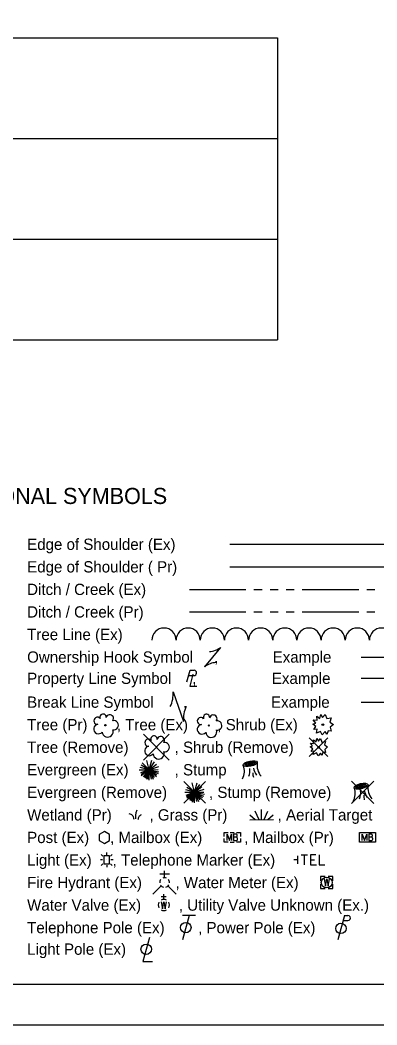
# Model space of a CAD drawing. Extents: x 0 to 34, y 0 to 22.
# Drawn here: x 8.09 to 12.52, y 0 to 12.48 of the extents above; entities that cross this region are included whole.
import ezdxf

# ---------------------------------------------------------------- set-up
doc = ezdxf.new("R2010")
doc.units = 0
for name, color, linetype in [('Default', 7, 'Continuous'), ('SH_Border', 7, 'Continuous'), ('SH_Cut_Line', 7, 'Continuous'), ('SH_Text', 7, 'Continuous')]:
    doc.layers.add(name, color=color, linetype=linetype)

msp = doc.modelspace()

# ---------------------------------------------------------------- linework, layer by layer
at = {"layer": 'Default'}
for p, q in [((6.983, 12.257), (11.289, 12.257)), ((11.289, 12.257), (11.289, 11.007)), ((6.983, 11.007), (11.289, 11.007)), ((6.983, 11.007), (11.289, 11.007)), ((11.289, 11.007), (11.289, 9.757)), ((6.983, 9.757), (11.289, 9.757)), ((6.983, 9.757), (11.289, 9.757)), ((11.289, 9.757), (11.289, 8.507)), ((6.983, 8.507), (11.289, 8.507))]:
    msp.add_line(p, q, dxfattribs=at)
at = {"layer": 'SH_Border'}
msp.add_lwpolyline([(1.5, 21.5), (33.5, 21.5), (33.5, 0.5), (1.5, 0.5)], close=True, dxfattribs=at)
at = {"layer": 'SH_Cut_Line'}
msp.add_lwpolyline([(0, 0), (34, 0), (34, 22), (0, 22)], close=True, dxfattribs=at)
at = {"layer": 'SH_Text'}
for p, q in [((10.698, 5.968), (14.181, 5.968)), ((10.698, 5.688), (14.181, 5.688)), ((10.197, 5.408), (10.897, 5.408)), ((10.997, 5.408), (11.097, 5.408)), ((11.197, 5.408), (11.297, 5.408)), ((11.397, 5.408), (11.497, 5.408)), ((11.597, 5.408), (12.297, 5.408)), ((12.397, 5.408), (12.497, 5.408)), ((10.197, 5.128), (10.897, 5.128)), ((10.997, 5.128), (11.097, 5.128)), ((11.197, 5.128), (11.297, 5.128)), ((11.397, 5.128), (11.497, 5.128)), ((11.597, 5.128), (12.297, 5.128)), ((12.397, 5.128), (12.497, 5.128)), ((10.385, 4.448), (10.585, 4.688)), ((10.485, 4.568), (10.485, 4.568)), ((12.328, 4.568), (14.11, 4.568)), ((10.185, 4.337), (10.25, 4.337)), ((10.225, 4.306), (10.225, 4.306)), ((12.328, 4.304), (14.11, 4.304)), ((9.992, 4.137), (10.122, 3.769)), ((12.328, 4.008), (13.093, 4.008)), ((10.057, 3.953), (10.057, 3.953)), ((9.625, 3.609), (9.946, 3.288)), ((9.946, 3.609), (9.625, 3.288)), ((11.684, 3.564), (11.916, 3.333)), ((11.916, 3.564), (11.684, 3.333)), ((9.786, 3.448), (9.786, 3.448)), ((11.8, 3.448), (11.8, 3.448)), ((9.696, 3.168), (9.609, 3.255)), ((9.696, 3.168), (9.665, 3.284)), ((9.696, 3.168), (9.727, 3.286)), ((9.696, 3.168), (9.762, 3.265)), ((9.573, 3.168), (9.696, 3.168)), ((9.696, 3.168), (9.586, 3.198)), ((9.696, 3.168), (9.589, 3.129)), ((9.696, 3.168), (9.596, 3.111)), ((9.696, 3.168), (9.598, 3.226)), ((9.696, 3.168), (9.598, 3.093)), ((9.696, 3.168), (9.622, 3.082)), ((9.696, 3.168), (9.638, 3.068)), ((9.696, 3.168), (9.654, 3.06)), ((9.696, 3.168), (9.664, 3.047)), ((9.696, 3.168), (9.683, 3.053)), ((9.696, 3.168), (9.787, 3.238)), ((9.696, 3.168), (9.814, 3.208)), ((9.696, 3.168), (9.809, 3.17)), ((9.696, 3.037), (9.696, 3.168)), ((9.696, 3.168), (9.719, 3.052)), ((9.696, 3.168), (9.744, 3.051)), ((9.696, 3.168), (9.759, 3.073)), ((9.696, 3.168), (9.786, 3.08)), ((9.696, 3.168), (9.792, 3.104)), ((9.696, 3.168), (9.808, 3.12)), ((9.696, 3.168), (9.817, 3.144)), ((10.97, 3.168), (10.97, 3.168)), ((10.126, 3.022), (10.394, 2.755)), ((10.394, 3.022), (10.126, 2.755)), ((10.26, 2.888), (10.229, 3.004)), ((10.26, 2.888), (10.291, 3.006)), ((12.206, 3.027), (12.484, 2.749)), ((12.484, 3.027), (12.206, 2.749)), ((10.137, 2.888), (10.26, 2.888)), ((10.26, 2.888), (10.15, 2.918)), ((10.26, 2.888), (10.153, 2.849)), ((10.26, 2.888), (10.16, 2.831)), ((10.26, 2.888), (10.162, 2.946)), ((10.26, 2.888), (10.162, 2.814)), ((10.26, 2.888), (10.173, 2.976)), ((10.26, 2.888), (10.186, 2.802)), ((10.26, 2.888), (10.202, 2.788)), ((10.26, 2.888), (10.218, 2.78)), ((10.26, 2.888), (10.228, 2.767)), ((10.26, 2.888), (10.247, 2.774)), ((10.26, 2.888), (10.326, 2.986)), ((10.26, 2.888), (10.351, 2.959)), ((10.26, 2.888), (10.378, 2.929)), ((10.26, 2.888), (10.373, 2.891)), ((10.26, 2.757), (10.26, 2.888)), ((10.26, 2.888), (10.283, 2.773)), ((10.26, 2.888), (10.308, 2.772)), ((10.26, 2.888), (10.323, 2.794)), ((10.26, 2.888), (10.35, 2.8)), ((10.26, 2.888), (10.356, 2.825)), ((10.26, 2.888), (10.372, 2.84)), ((10.26, 2.888), (10.381, 2.864)), ((10.26, 2.888), (10.26, 2.888)), ((12.345, 2.888), (12.345, 2.888)), ((12.345, 2.888), (12.345, 2.888)), ((11.062, 2.548), (11.01, 2.654)), ((11.092, 2.548), (11.09, 2.674)), ((11.122, 2.549), (11.171, 2.656)), ((11.013, 2.547), (10.945, 2.604)), ((10.946, 2.546), (11.238, 2.551)), ((11.17, 2.55), (11.237, 2.609)), ((10.703, 2.39), (10.753, 2.39)), ((10.703, 2.267), (10.753, 2.267)), ((10.728, 2.328), (10.728, 2.328)), ((12.407, 2.328), (12.407, 2.328)), ((9.169, 2.112), (9.169, 2.139)), ((9.117, 2.049), (9.09, 2.049)), ((9.121, 2.097), (9.102, 2.116)), ((9.121, 2), (9.102, 1.981)), ((9.169, 2.048), (9.169, 2.048)), ((9.235, 2.116), (9.217, 2.097)), ((9.235, 1.981), (9.217, 2)), ((9.248, 2.049), (9.221, 2.049)), ((11.541, 2.048), (11.492, 2.048)), ((11.541, 1.998), (11.541, 2.098)), ((9.169, 1.984), (9.169, 1.958)), ((9.947, 1.872), (9.827, 1.872)), ((9.887, 1.829), (9.887, 1.915)), ((9.887, 1.768), (9.887, 1.768)), ((9.887, 1.768), (9.887, 1.768)), ((11.9, 1.768), (11.9, 1.768)), ((9.845, 1.726), (9.741, 1.622)), ((9.878, 1.558), (9.878, 1.622)), ((9.929, 1.726), (10.033, 1.622)), ((9.909, 1.59), (9.846, 1.59)), ((9.878, 1.488), (9.878, 1.488)), ((10.191, 1.358), (10.11, 1.058)), ((10.271, 1.358), (10.111, 1.358)), ((12.12, 1.358), (12.039, 1.058)), ((12.103, 1.295), (12.162, 1.295)), ((12.12, 1.358), (12.162, 1.358))]:
    msp.add_line(p, q, dxfattribs=at)
for points in [[(10.164, 4.258), (10.203, 4.406), (10.255, 4.406)], [(10.238, 4.354), (10.199, 4.206), (10.286, 4.206)], [(11.849, 3.819), (11.879, 3.856), (11.9, 3.803), (11.954, 3.812), (11.938, 3.761), (11.985, 3.732), (11.942, 3.695), (11.954, 3.649), (11.917, 3.653), (11.901, 3.607), (11.879, 3.642), (11.845, 3.601), (11.824, 3.645), (11.773, 3.624), (11.782, 3.671), (11.742, 3.667), (11.765, 3.706), (11.727, 3.734), (11.764, 3.748), (11.734, 3.788), (11.78, 3.782), (11.779, 3.834), (11.816, 3.806), (11.827, 3.855), (11.849, 3.819)], [(11.797, 3.525), (11.822, 3.557), (11.84, 3.512), (11.886, 3.519), (11.872, 3.476), (11.912, 3.451), (11.876, 3.42), (11.886, 3.381), (11.854, 3.384), (11.84, 3.345), (11.822, 3.375), (11.793, 3.34), (11.775, 3.378), (11.732, 3.359), (11.74, 3.399), (11.706, 3.396), (11.726, 3.429), (11.693, 3.454), (11.724, 3.465), (11.699, 3.499), (11.738, 3.494), (11.737, 3.538), (11.769, 3.514), (11.778, 3.556), (11.797, 3.525)], [(9.076, 2.291), (9.14, 2.253), (9.205, 2.291), (9.205, 2.366), (9.14, 2.403), (9.076, 2.366), (9.076, 2.291)], [(10.628, 2.341), (10.628, 2.39), (10.677, 2.39)], [(10.779, 2.39), (10.828, 2.39), (10.828, 2.341)], [(10.677, 2.267), (10.628, 2.267), (10.628, 2.316)], [(10.664, 2.288), (10.664, 2.368), (10.693, 2.288), (10.72, 2.368), (10.72, 2.288)], [(10.78, 2.332), (10.783, 2.335), (10.785, 2.337), (10.786, 2.339), (10.786, 2.34), (10.788, 2.343), (10.788, 2.344), (10.79, 2.349), (10.79, 2.351), (10.79, 2.353), (10.789, 2.357), (10.788, 2.36), (10.786, 2.363), (10.783, 2.365), (10.78, 2.367), (10.779, 2.367), (10.776, 2.368), (10.745, 2.368), (10.745, 2.288), (10.78, 2.288), (10.784, 2.291), (10.788, 2.294), (10.791, 2.299), (10.793, 2.305), (10.793, 2.31), (10.793, 2.314), (10.792, 2.318), (10.79, 2.324), (10.786, 2.327), (10.78, 2.332), (10.745, 2.332)], [(10.828, 2.316), (10.828, 2.267), (10.779, 2.267)], [(12.342, 2.288), (12.342, 2.368), (12.371, 2.288), (12.398, 2.368), (12.398, 2.288)], [(12.458, 2.332), (12.461, 2.335), (12.463, 2.337), (12.464, 2.339), (12.465, 2.34), (12.466, 2.343), (12.466, 2.344), (12.468, 2.349), (12.468, 2.351), (12.468, 2.353), (12.467, 2.357), (12.466, 2.36), (12.464, 2.363), (12.461, 2.365), (12.458, 2.367), (12.457, 2.367), (12.454, 2.368), (12.423, 2.368), (12.423, 2.288), (12.458, 2.288), (12.462, 2.291), (12.466, 2.294), (12.469, 2.299), (12.471, 2.305), (12.471, 2.31), (12.471, 2.314), (12.47, 2.318), (12.468, 2.324), (12.465, 2.327), (12.458, 2.332), (12.423, 2.332)], [(11.582, 2.111), (11.66, 2.111)], [(11.622, 2.111), (11.622, 1.986)], [(11.767, 2.111), (11.699, 2.111), (11.699, 1.986), (11.772, 1.986)], [(11.699, 2.048), (11.748, 2.048)], [(11.807, 2.111), (11.807, 1.986), (11.875, 1.986)], [(11.88, 1.843), (11.825, 1.843), (11.825, 1.788)], [(11.825, 1.748), (11.825, 1.693), (11.88, 1.693)], [(11.867, 1.813), (11.884, 1.723), (11.9, 1.813), (11.917, 1.723), (11.934, 1.813)], [(11.975, 1.788), (11.975, 1.843), (11.92, 1.843)], [(11.92, 1.693), (11.975, 1.693), (11.975, 1.748)], [(9.846, 1.529), (9.862, 1.443), (9.878, 1.529), (9.894, 1.443), (9.91, 1.529)], [(9.698, 1.087), (9.619, 0.788), (9.737, 0.788)]]:
    msp.add_lwpolyline(points, dxfattribs=at)
for points in [[(12.307, 2.39), (12.507, 2.39), (12.507, 2.267), (12.307, 2.267)], [(9.135, 1.998), (9.202, 1.998), (9.202, 2.098), (9.135, 2.098)]]:
    msp.add_lwpolyline(points, close=True, dxfattribs=at)
for centre, radius in [((9.153, 3.72), 0.0084), ((10.437, 3.717), 0.0072), ((11.853, 3.728), 0.0115), ((9.786, 3.448), 0.0072), ((11.8, 3.448), 0.00979), ((11.9, 1.768), 0.0675), ((10.151, 1.208), 0.065), ((12.077, 1.198), 0.065), ((9.659, 0.939), 0.065)]:
    msp.add_circle(centre, radius, dxfattribs=at)
for centre, radius, start, end in [((9.88, 4.778), 0.15, 0.0098, 179.9926), ((10.18, 4.778), 0.15, 0.0098, 179.9926), ((10.48, 4.778), 0.15, 0.0098, 179.9926), ((10.78, 4.778), 0.15, 0.0098, 179.9926), ((11.08, 4.778), 0.15, 0.0098, 179.9926), ((11.38, 4.778), 0.15, 0.0098, 179.9926), ((11.68, 4.778), 0.15, 0.0098, 179.9926), ((11.98, 4.778), 0.15, 0.0098, 179.9926), ((12.28, 4.778), 0.15, 0.0098, 179.9926), ((12.58, 4.778), 0.15, 0.0098, 179.9926), ((10.427, 4.903), 0.267, 273.6945, 306.337), ((10.543, 4.233), 0.267, 93.6945, 126.337), ((10.25, 4.372), 0.0345, 270.471, 81.3281), ((9.66, 4.105), 0.334, 332.9422, 5.5848), ((10.454, 3.801), 0.334, 152.9422, 185.5848), ((9.053, 3.776), 0.0441, 39.0625, 279.5412), ((9.123, 3.821), 0.0395, 354.0047, 205.9741), ((9.207, 3.805), 0.0466, 323.83, 165.0376), ((9.256, 3.721), 0.0574, 259.1453, 101.4596), ((10.338, 3.773), 0.0441, 39.0625, 279.5412), ((10.408, 3.818), 0.0395, 354.0047, 205.9741), ((10.492, 3.802), 0.0466, 323.83, 165.0376), ((10.541, 3.718), 0.0574, 259.1453, 101.4596), ((9.067, 3.674), 0.0592, 96.1722, 320.5737), ((9.181, 3.642), 0.0685, 184.9476, 19.4572), ((10.352, 3.67), 0.0592, 96.1722, 320.5737), ((10.466, 3.639), 0.0685, 184.9476, 19.4572), ((9.686, 3.504), 0.0441, 39.0625, 279.5412), ((9.756, 3.549), 0.0395, 354.0047, 205.9741), ((9.84, 3.533), 0.0466, 323.83, 165.0376), ((9.889, 3.449), 0.0574, 259.1453, 101.4596), ((9.7, 3.402), 0.0592, 96.1722, 320.5737), ((9.814, 3.37), 0.0685, 184.9476, 19.4572), ((11.25, 3.225), 0.215, 171.4106, 219.9194), ((10.678, 3.151), 0.2, 331.5338, 20.9269), ((10.694, 3.17), 0.253, 340.7938, 3.5481), ((11.165, 3.128), 0.182, 178.7926, 197.1224), ((11.295, 3.271), 0.316, 194.9653, 212.1216), ((12.054, 2.871), 0.2, 331.5338, 20.9269), ((12.069, 2.89), 0.253, 340.7938, 3.5481), ((12.671, 2.991), 0.316, 194.9653, 212.1216), ((12.626, 2.945), 0.215, 171.4106, 219.9194), ((12.541, 2.848), 0.182, 178.7926, 197.1224), ((9.887, 1.768), 0.06, 140.021, 184.0629), ((9.887, 1.768), 0.06, 68.1395, 112.038), ((9.887, 1.768), 0.06, 356.0165, 39.9889), ((9.887, 1.768), 0.06, 211.8788, 255.8479), ((9.887, 1.768), 0.06, 283.8239, 329.9097), ((9.878, 1.489), 0.07, 150.0184, 209.9816), ((9.878, 1.489), 0.07, 60.0184, 120.0157), ((9.878, 1.489), 0.07, 330.0184, 29.9816), ((9.878, 1.489), 0.07, 239.9843, 299.9816), ((12.163, 1.327), 0.0319, 268.8767, 91.1233)]:
    msp.add_arc(centre, radius, start, end, dxfattribs=at)
for centre, major_axis in [((10.951, 3.244), (0.0868, 0.0187)), ((10.951, 3.244), (0.0651, 0.0141)), ((10.951, 3.244), (0.0488, 0.0105)), ((10.951, 3.244), (0.0275, 0.0059)), ((10.951, 3.244), (0.0154, 0.0033)), ((12.327, 2.964), (0.0868, 0.0187)), ((12.327, 2.964), (0.0651, 0.0141)), ((12.327, 2.964), (0.0488, 0.0105)), ((12.327, 2.964), (0.0275, 0.0059)), ((12.327, 2.964), (0.0154, 0.0033))]:
    msp.add_ellipse(centre, major_axis=major_axis, ratio=0.36865, dxfattribs=at)
for points in [[(9.445, 2.624), (9.486, 2.606), (9.504, 2.553)], [(9.532, 2.557), (9.532, 2.604), (9.538, 2.649), (9.547, 2.669)], [(9.56, 2.55), (9.572, 2.588), (9.601, 2.612)]]:
    msp.add_spline(points, degree=3, dxfattribs=at)

# ---------------------------------------------------------------- texts
for s, height, p in [('CONVENTIONAL SYMBOLS', 0.2, (6.442, 6.468)), ('Edge of Shoulder (Ex)', 0.14, (8.181, 5.898)), ('Edge of Shoulder ( Pr)', 0.14, (8.181, 5.618)), ('Ditch / Creek (Ex)', 0.14, (8.181, 5.338)), ('Ditch / Creek (Pr)', 0.14, (8.181, 5.058)), ('Tree Line (Ex)', 0.14, (8.181, 4.778)), ('Ownership Hook Symbol     ,             Example', 0.14, (8.181, 4.498)), ('Property Line Symbol     ,                  Example', 0.14, (8.181, 4.234)), ('Break Line Symbol       ,                    Example', 0.14, (8.181, 3.938)), ('Tree (Pr)       , Tree (Ex)       , Shrub (Ex)', 0.14, (8.181, 3.658)), ('Tree (Remove)           , Shrub (Remove)', 0.14, (8.181, 3.378)), ('Evergreen (Ex)           , Stump ', 0.14, (8.181, 3.098)), ('Evergreen (Remove)          , Stump (Remove)', 0.14, (8.181, 2.818)), ('Wetland (Pr)         , Grass (Pr)            , Aerial Target    ', 0.14, (8.181, 2.538)), ('Post (Ex)     , Mailbox (Ex)          , Mailbox (Pr)', 0.14, (8.181, 2.258)), ('Light (Ex)     , Telephone Marker (Ex)     ', 0.14, (8.181, 1.978)), ('Fire Hydrant (Ex)        , Water Meter (Ex)', 0.14, (8.181, 1.698)), ('Water Valve (Ex)         , Utility Valve Unknown (Ex.)', 0.14, (8.181, 1.418)), ('Telephone Pole (Ex)        , Power Pole (Ex)', 0.14, (8.181, 1.138)), ('Light Pole (Ex)     ', 0.14, (8.181, 0.871))]:
    msp.add_text(s, height=height, dxfattribs=at).set_placement(p)

doc.saveas('drawing.dxf')
